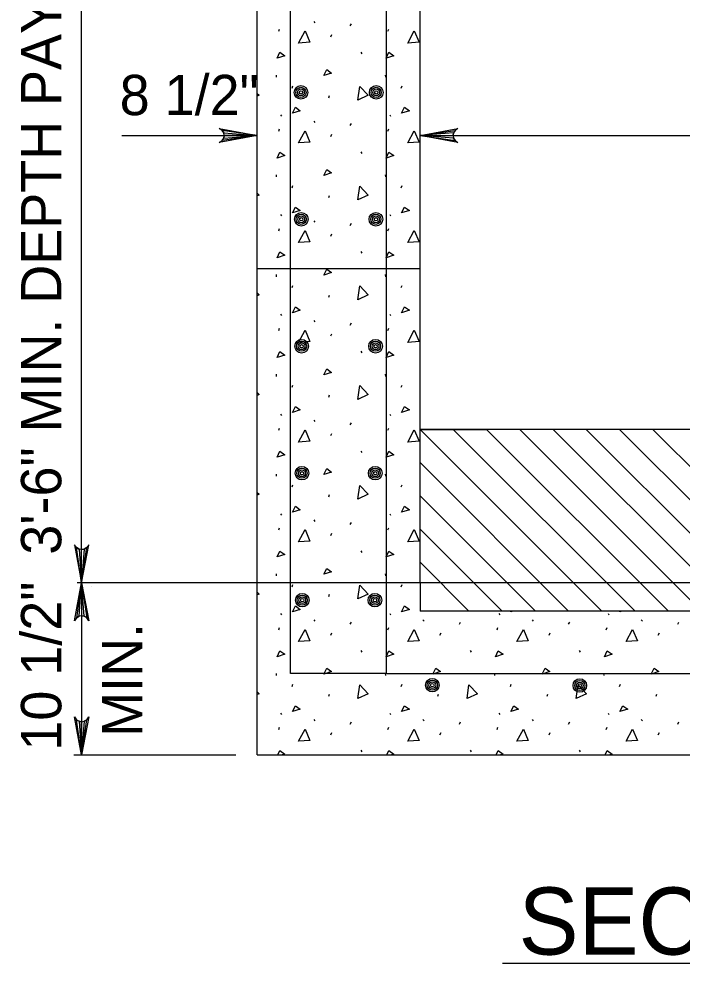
# Model space of a CAD drawing. Extents: x 2.4 to 9.7, y 1.1 to 11.2.
# Drawn here: x 2.42 to 3.407, y 8.252 to 9.657 of the extents above; entities that cross this region are included whole.
import ezdxf

# ---------------------------------------------------------------- set-up
doc = ezdxf.new("R2010")
doc.units = 0
for name, color, linetype in [('DETL-DIMS', 7, 'Continuous'), ('DETL-LINE', 7, 'Continuous'), ('DETL-NOTE', 7, 'Continuous'), ('DETL-PATT', 7, 'Continuous'), ('DETL-TITL', 7, 'Continuous')]:
    doc.layers.add(name, color=color, linetype=linetype)

msp = doc.modelspace()

# ---------------------------------------------------------------- linework, layer by layer
at = {"layer": 'DETL-DIMS'}
for p, q in [((2.5136, 8.8122), (2.5136, 10.2215)), ((2.5733, 9.4838), (2.7749, 9.4838)), ((3.0173, 9.4838), (4.49, 9.4838)), ((3.6529, 8.8182), (2.5069, 8.8182)), ((2.5136, 8.8122), (2.5136, 8.5621)), ((2.528, 8.8122), (2.528, 8.8122)), ((2.502, 8.5621), (2.7433, 8.5621))]:
    msp.add_line(p, q, dxfattribs=at)
for points in [[(2.7749, 9.4838), (2.7184, 9.4732), (2.7227, 9.4762), (2.725, 9.48), (2.7256, 9.4838), (2.725, 9.4876), (2.7227, 9.4914), (2.7184, 9.4944), (2.7749, 9.4838), (2.7227, 9.4914), (2.725, 9.4876), (2.7749, 9.4838), (2.7256, 9.4838), (2.725, 9.48), (2.7749, 9.4838), (2.7227, 9.4762)], [(3.0173, 9.4838), (3.0738, 9.4944), (3.0694, 9.4914), (3.0672, 9.4876), (3.0665, 9.4838), (3.0672, 9.48), (3.0694, 9.4762), (3.0738, 9.4732), (3.0173, 9.4838), (3.0694, 9.4762), (3.0672, 9.48), (3.0173, 9.4838), (3.0665, 9.4838), (3.0672, 9.4876), (3.0173, 9.4838), (3.0694, 9.4914)], [(2.5136, 8.8182), (2.5242, 8.8747), (2.5212, 8.8704), (2.5174, 8.8681), (2.5136, 8.8675), (2.5099, 8.8681), (2.5061, 8.8704), (2.5031, 8.8747), (2.5136, 8.8182), (2.5061, 8.8704), (2.5099, 8.8681), (2.5136, 8.8182), (2.5136, 8.8675), (2.5174, 8.8681), (2.5136, 8.8182), (2.5212, 8.8704)], [(2.5136, 8.8182), (2.5242, 8.7617), (2.5212, 8.7661), (2.5174, 8.7683), (2.5136, 8.769), (2.5099, 8.7683), (2.5061, 8.7661), (2.5031, 8.7617), (2.5136, 8.8182), (2.5061, 8.7661), (2.5099, 8.7683), (2.5136, 8.8182), (2.5136, 8.769), (2.5174, 8.7683), (2.5136, 8.8182), (2.5212, 8.7661)], [(2.5136, 8.5621), (2.5031, 8.6186), (2.5061, 8.6142), (2.5099, 8.612), (2.5136, 8.6113), (2.5174, 8.612), (2.5212, 8.6142), (2.5242, 8.6186), (2.5136, 8.5621), (2.5212, 8.6142), (2.5174, 8.612), (2.5136, 8.5621), (2.5136, 8.6113), (2.5099, 8.612), (2.5136, 8.5621), (2.5061, 8.6142)]]:
    msp.add_lwpolyline(points, dxfattribs=at)
at = {"layer": 'DETL-LINE'}
for p, q in [((2.7749, 8.5621), (2.7749, 10.2215)), ((3.0173, 8.8182), (3.0173, 10.1963)), ((2.8247, 8.6833), (2.8247, 9.9687)), ((2.9674, 8.6833), (2.9674, 9.9687)), ((4.49, 9.0465), (3.0173, 9.0465)), ((3.0173, 9.0465), (3.1163, 9.0465)), ((4.49, 8.8182), (3.0173, 8.8182)), ((3.0173, 8.8182), (3.0173, 8.7758)), ((4.49, 8.7758), (3.0173, 8.7758)), ((2.9674, 8.6833), (4.531, 8.6833)), ((2.7749, 8.5621), (4.7324, 8.5621))]:
    msp.add_line(p, q, dxfattribs=at)
msp.add_lwpolyline([(2.9674, 8.6833), (2.8961, 8.6833), (2.8247, 8.6833)], dxfattribs=at)
for centre, radius in [((2.84, 9.548), 0.0101), ((2.9521, 9.548), 0.0101), ((2.84, 9.548), 0.00758), ((2.84, 9.548), 0.00505), ((2.84, 9.548), 0.00253), ((2.9521, 9.548), 0.00758), ((2.9521, 9.548), 0.00505), ((2.9521, 9.548), 0.00253), ((2.8405, 9.3591), 0.0101), ((2.8405, 9.3591), 0.00758), ((2.8405, 9.3591), 0.00505), ((2.8405, 9.3591), 0.00253), ((2.9516, 9.3591), 0.0101), ((2.9516, 9.3591), 0.00758), ((2.9516, 9.3591), 0.00505), ((2.9516, 9.3591), 0.00253), ((2.841, 9.1702), 0.0101), ((2.841, 9.1702), 0.00758), ((2.9511, 9.1702), 0.0101), ((2.9511, 9.1702), 0.00758), ((2.841, 9.1702), 0.00505), ((2.841, 9.1702), 0.00253), ((2.9511, 9.1702), 0.00505), ((2.9511, 9.1702), 0.00253), ((2.8415, 8.9812), 0.0101), ((2.8415, 8.9812), 0.00758), ((2.8415, 8.9812), 0.00505), ((2.8415, 8.9812), 0.00253), ((2.9506, 8.9812), 0.0101), ((2.9506, 8.9812), 0.00758), ((2.9506, 8.9812), 0.00505), ((2.9506, 8.9812), 0.00253), ((2.842, 8.7923), 0.0101), ((2.842, 8.7923), 0.00758), ((2.842, 8.7923), 0.00505), ((2.9501, 8.7923), 0.0101), ((2.9501, 8.7923), 0.00758), ((2.9501, 8.7923), 0.00505), ((2.842, 8.7923), 0.00253), ((2.9501, 8.7923), 0.00253), ((3.0356, 8.6657), 0.0101), ((3.0356, 8.6657), 0.00758), ((3.0356, 8.6657), 0.00505), ((3.2551, 8.6653), 0.0101), ((3.2551, 8.6653), 0.00758), ((3.0356, 8.6657), 0.00253), ((3.2551, 8.6653), 0.00505), ((3.2551, 8.6653), 0.00253)]:
    msp.add_circle(centre, radius, dxfattribs=at)
at = {"layer": 'DETL-PATT'}
for p, q in [((2.8069, 9.639), (2.8082, 9.6422)), ((2.8591, 9.6537), (2.8608, 9.6517)), ((2.9135, 9.6469), (2.9151, 9.6501)), ((2.9694, 9.639), (2.9707, 9.6422)), ((2.8845, 9.6309), (2.8861, 9.6341)), ((2.9292, 9.608), (2.9308, 9.6056)), ((2.8029, 9.5737), (2.8033, 9.5705)), ((2.9654, 9.5737), (2.9658, 9.5705)), ((2.8269, 9.5544), (2.8281, 9.5576)), ((2.9894, 9.5544), (2.9906, 9.5576)), ((2.8813, 9.5399), (2.8825, 9.5432)), ((2.8098, 9.5146), (2.811, 9.5126)), ((2.9723, 9.5146), (2.9735, 9.5126)), ((2.8591, 9.5053), (2.8608, 9.5033)), ((2.9135, 9.4985), (2.9151, 9.5017)), ((2.8069, 9.4905), (2.8082, 9.4937)), ((2.8845, 9.4825), (2.8861, 9.4857)), ((2.9694, 9.4905), (2.9707, 9.4937)), ((2.9292, 9.4595), (2.9308, 9.4571)), ((2.8029, 9.4253), (2.8033, 9.4221)), ((2.9654, 9.4253), (2.9658, 9.4221)), ((2.8269, 9.406), (2.8281, 9.4092)), ((2.9894, 9.406), (2.9906, 9.4092)), ((2.8813, 9.3915), (2.8825, 9.3947)), ((2.8098, 9.3661), (2.811, 9.3641)), ((2.9723, 9.3661), (2.9735, 9.3641)), ((2.8069, 9.3421), (2.8082, 9.3453)), ((2.8591, 9.3569), (2.8608, 9.3549)), ((2.9135, 9.35), (2.9151, 9.3532)), ((2.9694, 9.3421), (2.9707, 9.3453)), ((2.8845, 9.334), (2.8861, 9.3373)), ((2.9292, 9.3111), (2.9308, 9.3087)), ((2.7749, 9.2858), (3.0173, 9.2858)), ((2.8029, 9.2769), (2.8033, 9.2737)), ((2.9654, 9.2769), (2.9658, 9.2737)), ((2.8269, 9.2575), (2.8281, 9.2608)), ((2.9894, 9.2575), (2.9906, 9.2608)), ((2.8813, 9.2431), (2.8825, 9.2463)), ((2.8098, 9.2177), (2.811, 9.2157)), ((2.8591, 9.2084), (2.8608, 9.2064)), ((2.9135, 9.2016), (2.9151, 9.2048)), ((2.9723, 9.2177), (2.9735, 9.2157)), ((2.8069, 9.1937), (2.8082, 9.1969)), ((2.9694, 9.1937), (2.9707, 9.1969)), ((2.8845, 9.1856), (2.8861, 9.1888)), ((2.9292, 9.1627), (2.9308, 9.1602)), ((2.8029, 9.1284), (2.8033, 9.1252)), ((2.9654, 9.1284), (2.9658, 9.1252)), ((2.8269, 9.1091), (2.8281, 9.1123)), ((2.9894, 9.1091), (2.9906, 9.1123)), ((2.8813, 9.0946), (2.8825, 9.0978)), ((2.8098, 9.0693), (2.811, 9.0672)), ((2.9723, 9.0693), (2.9735, 9.0672)), ((2.8591, 9.06), (2.8608, 9.058)), ((2.9135, 9.0532), (2.9151, 9.0564)), ((2.8069, 9.0452), (2.8082, 9.0484)), ((2.8845, 9.0372), (2.8861, 9.0404)), ((2.9694, 9.0452), (2.9707, 9.0484)), ((3.0173, 9.0465), (3.288, 8.7758)), ((3.0668, 9.0465), (3.3375, 8.7758)), ((3.1163, 9.0465), (3.387, 8.7758)), ((3.1658, 9.0465), (3.4365, 8.7758)), ((3.2153, 9.0465), (3.486, 8.7758)), ((3.2648, 9.0465), (3.5355, 8.7758)), ((3.3143, 9.0465), (3.585, 8.7758)), ((3.3638, 9.0465), (3.5921, 8.8182)), ((2.9292, 9.0142), (2.9308, 9.0118)), ((3.0173, 8.9971), (3.2385, 8.7758)), ((2.8029, 8.98), (2.8033, 8.9768)), ((2.9654, 8.98), (2.9658, 8.9768)), ((2.8269, 8.9607), (2.8281, 8.9639)), ((2.9894, 8.9607), (2.9906, 8.9639)), ((2.8813, 8.9462), (2.8825, 8.9494)), ((3.0173, 8.9476), (3.189, 8.7758)), ((2.8098, 8.9208), (2.811, 8.9188)), ((2.8591, 8.9116), (2.8608, 8.9095)), ((2.9723, 8.9208), (2.9735, 8.9188)), ((2.8069, 8.8968), (2.8082, 8.9)), ((2.9135, 8.9047), (2.9151, 8.9079)), ((2.9694, 8.8968), (2.9707, 8.9)), ((3.0173, 8.8981), (3.1396, 8.7758)), ((2.8845, 8.8887), (2.8861, 8.8919)), ((2.9292, 8.8658), (2.9308, 8.8634)), ((3.0173, 8.8486), (3.0901, 8.7758)), ((2.8029, 8.8316), (2.8033, 8.8283)), ((2.9654, 8.8316), (2.9658, 8.8283)), ((2.8269, 8.8122), (2.8281, 8.8155)), ((2.9894, 8.8122), (2.9906, 8.8155)), ((2.8813, 8.7977), (2.8825, 8.801)), ((2.8098, 8.7724), (2.811, 8.7704)), ((2.9723, 8.7724), (2.9735, 8.7704)), ((3.1348, 8.7724), (3.136, 8.7704)), ((3.2973, 8.7724), (3.2985, 8.7704)), ((2.8591, 8.7631), (2.8608, 8.7611)), ((2.9135, 8.7563), (2.9151, 8.7595)), ((3.0216, 8.7631), (3.0233, 8.7611)), ((3.076, 8.7563), (3.0776, 8.7595)), ((3.1841, 8.7631), (3.1858, 8.7611)), ((3.2385, 8.7563), (3.2401, 8.7595)), ((3.3466, 8.7631), (3.3483, 8.7611)), ((3.401, 8.7563), (3.4026, 8.7595)), ((2.8069, 8.7483), (2.8082, 8.7516)), ((2.8845, 8.7403), (2.8861, 8.7435)), ((2.9694, 8.7483), (2.9707, 8.7516)), ((3.047, 8.7403), (3.0486, 8.7435)), ((3.1319, 8.7483), (3.1332, 8.7516)), ((3.2095, 8.7403), (3.2111, 8.7435)), ((3.2944, 8.7483), (3.2957, 8.7516)), ((3.372, 8.7403), (3.3736, 8.7435)), ((2.9292, 8.7173), (2.9308, 8.7149)), ((3.0917, 8.7173), (3.0933, 8.7149)), ((3.2542, 8.7173), (3.2558, 8.7149)), ((2.8029, 8.6831), (2.8033, 8.6799)), ((2.9654, 8.6831), (2.9658, 8.6799)), ((3.1279, 8.6831), (3.1283, 8.6799)), ((3.2904, 8.6831), (3.2908, 8.6799)), ((2.8269, 8.6638), (2.8281, 8.667)), ((2.9894, 8.6638), (2.9906, 8.667)), ((3.1519, 8.6638), (3.1531, 8.667)), ((3.3144, 8.6638), (3.3156, 8.667)), ((2.8813, 8.6493), (2.8825, 8.6525)), ((3.0438, 8.6493), (3.045, 8.6525)), ((3.2063, 8.6493), (3.2075, 8.6525)), ((3.3688, 8.6493), (3.37, 8.6525)), ((2.8098, 8.6239), (2.811, 8.6219)), ((2.8591, 8.6147), (2.8608, 8.6127)), ((2.9723, 8.6239), (2.9735, 8.6219)), ((3.0216, 8.6147), (3.0233, 8.6127)), ((3.1348, 8.6239), (3.136, 8.6219)), ((3.1841, 8.6147), (3.1858, 8.6127)), ((3.2973, 8.6239), (3.2985, 8.6219)), ((3.3466, 8.6147), (3.3483, 8.6127)), ((2.8069, 8.5999), (2.8082, 8.6031)), ((2.9135, 8.6078), (2.9151, 8.6111)), ((2.9694, 8.5999), (2.9707, 8.6031)), ((3.076, 8.6078), (3.0776, 8.6111)), ((3.1319, 8.5999), (3.1332, 8.6031)), ((3.2385, 8.6078), (3.2401, 8.6111)), ((3.2944, 8.5999), (3.2957, 8.6031)), ((3.401, 8.6078), (3.4026, 8.6111)), ((2.8845, 8.5919), (2.8861, 8.5951)), ((3.047, 8.5919), (3.0486, 8.5951)), ((3.2095, 8.5919), (3.2111, 8.5951)), ((3.372, 8.5919), (3.3736, 8.5951)), ((2.9292, 8.5689), (2.9308, 8.5665)), ((3.0917, 8.5689), (3.0933, 8.5665)), ((3.2542, 8.5689), (3.2558, 8.5665))]:
    msp.add_line(p, q, dxfattribs=at)
for points in [[(2.8366, 9.6213), (2.8463, 9.6394), (2.8535, 9.6225), (2.8366, 9.6213)], [(2.9991, 9.6213), (3.0088, 9.6394), (3.016, 9.6225), (2.9991, 9.6213)], [(2.8045, 9.5987), (2.8086, 9.6076), (2.8158, 9.6023), (2.8045, 9.5987)], [(2.967, 9.5987), (2.9711, 9.6076), (2.9783, 9.6023), (2.967, 9.5987)], [(2.874, 9.5729), (2.8785, 9.5818), (2.8853, 9.5766), (2.874, 9.5729)], [(2.9248, 9.5363), (2.9276, 9.5568), (2.9401, 9.5436), (2.9248, 9.5363)], [(2.7749, 9.5464), (2.7776, 9.5436), (2.7749, 9.5423)], [(2.8273, 9.517), (2.8318, 9.5258), (2.839, 9.5206), (2.8273, 9.517)], [(2.9898, 9.517), (2.9943, 9.5258), (3.0015, 9.5206), (2.9898, 9.517)], [(2.8366, 9.4728), (2.8463, 9.4909), (2.8535, 9.474), (2.8366, 9.4728)], [(2.9991, 9.4728), (3.0088, 9.4909), (3.016, 9.474), (2.9991, 9.4728)], [(2.8045, 9.4503), (2.8086, 9.4591), (2.8158, 9.4539), (2.8045, 9.4503)], [(2.967, 9.4503), (2.9711, 9.4591), (2.9783, 9.4539), (2.967, 9.4503)], [(2.874, 9.4245), (2.8785, 9.4334), (2.8853, 9.4281), (2.874, 9.4245)], [(2.9248, 9.3879), (2.9276, 9.4084), (2.9401, 9.3951), (2.9248, 9.3879)], [(2.7749, 9.398), (2.7776, 9.3951), (2.7749, 9.3938)], [(2.8273, 9.3685), (2.8318, 9.3774), (2.839, 9.3722), (2.8273, 9.3685)], [(2.9898, 9.3685), (2.9943, 9.3774), (3.0015, 9.3722), (2.9898, 9.3685)], [(2.8366, 9.3244), (2.8463, 9.3425), (2.8535, 9.3256), (2.8366, 9.3244)], [(2.9991, 9.3244), (3.0088, 9.3425), (3.016, 9.3256), (2.9991, 9.3244)], [(2.8045, 9.3018), (2.8086, 9.3107), (2.8158, 9.3055), (2.8045, 9.3018)], [(2.967, 9.3018), (2.9711, 9.3107), (2.9783, 9.3055), (2.967, 9.3018)], [(2.874, 9.2761), (2.8785, 9.2849), (2.8853, 9.2797), (2.874, 9.2761)], [(2.7749, 9.2496), (2.7776, 9.2467), (2.7749, 9.2454)], [(2.9248, 9.2394), (2.9276, 9.26), (2.9401, 9.2467), (2.9248, 9.2394)], [(2.8273, 9.2201), (2.8318, 9.229), (2.839, 9.2237), (2.8273, 9.2201)], [(2.9898, 9.2201), (2.9943, 9.229), (3.0015, 9.2237), (2.9898, 9.2201)], [(2.8366, 9.1759), (2.8463, 9.1941), (2.8535, 9.1771), (2.8366, 9.1759)], [(2.9991, 9.1759), (3.0088, 9.1941), (3.016, 9.1771), (2.9991, 9.1759)], [(2.8045, 9.1534), (2.8086, 9.1623), (2.8158, 9.157), (2.8045, 9.1534)], [(2.967, 9.1534), (2.9711, 9.1623), (2.9783, 9.157), (2.967, 9.1534)], [(2.874, 9.1276), (2.8785, 9.1365), (2.8853, 9.1313), (2.874, 9.1276)], [(2.9248, 9.091), (2.9276, 9.1115), (2.9401, 9.0982), (2.9248, 9.091)], [(2.7749, 9.1011), (2.7776, 9.0982), (2.7749, 9.097)], [(2.8273, 9.0717), (2.8318, 9.0805), (2.839, 9.0753), (2.8273, 9.0717)], [(2.9898, 9.0717), (2.9943, 9.0805), (3.0015, 9.0753), (2.9898, 9.0717)], [(2.8366, 9.0275), (2.8463, 9.0456), (2.8535, 9.0287), (2.8366, 9.0275)], [(2.9991, 9.0275), (3.0088, 9.0456), (3.016, 9.0287), (2.9991, 9.0275)], [(2.8045, 9.005), (2.8086, 9.0138), (2.8158, 9.0086), (2.8045, 9.005)], [(2.967, 9.005), (2.9711, 9.0138), (2.9783, 9.0086), (2.967, 9.005)], [(2.874, 8.9792), (2.8785, 8.988), (2.8853, 8.9828), (2.874, 8.9792)], [(2.7749, 8.9527), (2.7776, 8.9498), (2.7749, 8.9485)], [(2.9248, 8.9426), (2.9276, 8.9631), (2.9401, 8.9498), (2.9248, 8.9426)], [(2.8273, 8.9232), (2.8318, 8.9321), (2.839, 8.9269), (2.8273, 8.9232)], [(2.9898, 8.9232), (2.9943, 8.9321), (3.0015, 8.9269), (2.9898, 8.9232)], [(2.8366, 8.8791), (2.8463, 8.8972), (2.8535, 8.8803), (2.8366, 8.8791)], [(2.9991, 8.8791), (3.0088, 8.8972), (3.016, 8.8803), (2.9991, 8.8791)], [(2.8045, 8.8565), (2.8086, 8.8654), (2.8158, 8.8601), (2.8045, 8.8565)], [(2.967, 8.8565), (2.9711, 8.8654), (2.9783, 8.8601), (2.967, 8.8565)], [(2.874, 8.8308), (2.8785, 8.8396), (2.8853, 8.8344), (2.874, 8.8308)], [(2.9248, 8.7941), (2.9276, 8.8147), (2.9401, 8.8014), (2.9248, 8.7941)], [(2.7749, 8.8042), (2.7776, 8.8014), (2.7749, 8.8001)], [(2.8273, 8.7748), (2.8318, 8.7837), (2.839, 8.7784), (2.8273, 8.7748)], [(2.9898, 8.7748), (2.9943, 8.7837), (3.0015, 8.7784), (2.9898, 8.7748)], [(3.1523, 8.7748), (3.1528, 8.7758)], [(3.1555, 8.7758), (3.1523, 8.7748)], [(3.3148, 8.7748), (3.3153, 8.7758)], [(3.318, 8.7758), (3.3148, 8.7748)], [(2.8366, 8.7306), (2.8463, 8.7487), (2.8535, 8.7318), (2.8366, 8.7306)], [(2.9991, 8.7306), (3.0088, 8.7487), (3.016, 8.7318), (2.9991, 8.7306)], [(3.1616, 8.7306), (3.1713, 8.7487), (3.1785, 8.7318), (3.1616, 8.7306)], [(3.3241, 8.7306), (3.3338, 8.7487), (3.341, 8.7318), (3.3241, 8.7306)], [(2.8045, 8.7081), (2.8086, 8.7169), (2.8158, 8.7117), (2.8045, 8.7081)], [(2.967, 8.7081), (2.9711, 8.7169), (2.9783, 8.7117), (2.967, 8.7081)], [(3.1295, 8.7081), (3.1336, 8.7169), (3.1408, 8.7117), (3.1295, 8.7081)], [(3.292, 8.7081), (3.2961, 8.7169), (3.3033, 8.7117), (3.292, 8.7081)], [(2.874, 8.6823), (2.8785, 8.6912), (2.8853, 8.6859), (2.874, 8.6823)], [(3.0365, 8.6823), (3.041, 8.6912), (3.0478, 8.6859), (3.0365, 8.6823)], [(3.199, 8.6823), (3.2035, 8.6912), (3.2103, 8.6859), (3.199, 8.6823)], [(3.3615, 8.6823), (3.366, 8.6912), (3.3728, 8.6859), (3.3615, 8.6823)], [(2.9248, 8.6457), (2.9276, 8.6662), (2.9401, 8.6529), (2.9248, 8.6457)], [(3.0873, 8.6457), (3.0901, 8.6662), (3.1026, 8.6529), (3.0873, 8.6457)], [(3.2498, 8.6457), (3.2526, 8.6662), (3.2651, 8.6529), (3.2498, 8.6457)], [(2.7749, 8.6558), (2.7776, 8.6529), (2.7749, 8.6517)], [(2.8273, 8.6264), (2.8318, 8.6352), (2.839, 8.63), (2.8273, 8.6264)], [(2.9898, 8.6264), (2.9943, 8.6352), (3.0015, 8.63), (2.9898, 8.6264)], [(3.1523, 8.6264), (3.1568, 8.6352), (3.164, 8.63), (3.1523, 8.6264)], [(3.3148, 8.6264), (3.3193, 8.6352), (3.3265, 8.63), (3.3148, 8.6264)], [(2.8366, 8.5822), (2.8463, 8.6003), (2.8535, 8.5834), (2.8366, 8.5822)], [(2.9991, 8.5822), (3.0088, 8.6003), (3.016, 8.5834), (2.9991, 8.5822)], [(3.1616, 8.5822), (3.1713, 8.6003), (3.1785, 8.5834), (3.1616, 8.5822)], [(3.3241, 8.5822), (3.3338, 8.6003), (3.341, 8.5834), (3.3241, 8.5822)], [(2.8056, 8.5621), (2.8086, 8.5685), (2.8158, 8.5633), (2.8122, 8.5621)], [(2.9681, 8.5621), (2.9711, 8.5685), (2.9783, 8.5633), (2.9747, 8.5621)], [(3.1306, 8.5621), (3.1336, 8.5685), (3.1408, 8.5633), (3.1372, 8.5621)], [(3.2931, 8.5621), (3.2961, 8.5685), (3.3033, 8.5633), (3.2997, 8.5621)]]:
    msp.add_lwpolyline(points, dxfattribs=at)
at = {"layer": 'DETL-TITL'}
msp.add_line((3.14, 8.2521), (4.1911, 8.2521), dxfattribs=at)

# ---------------------------------------------------------------- texts
at = {"layer": 'DETL-NOTE'}
for s, p in [('3\'-6" MIN. DEPTH PAYMENT', (2.4833, 8.8599)), ('10 1/2"', (2.4833, 8.5683)), ('MIN.', (2.6039, 8.5889))]:
    msp.add_text(s, height=0.06, rotation=90, dxfattribs=at).set_placement(p)
msp.add_text('8 1/2"', height=0.06, dxfattribs=at).set_placement((2.5702, 9.5141))
at = {"layer": 'DETL-TITL'}
msp.add_text('SECTION B-B', height=0.1, dxfattribs=at).set_placement((3.164, 8.2647))

doc.saveas('drawing.dxf')
